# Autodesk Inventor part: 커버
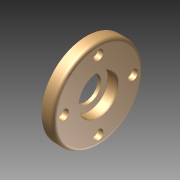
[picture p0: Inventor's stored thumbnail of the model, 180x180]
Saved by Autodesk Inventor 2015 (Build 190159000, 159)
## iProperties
Created: 2024-12
Part Number: 커버
Material: 일반
Document SubType Name: Modeling
Designer: 10401
Density: 1 g/cm^3
Appearance: 기본값
Author: 10401
Author: jhkim
Creation Date: 2024-11-28
Sending System: Autodesk Inventor 2025
Preprocessor: ST-DEVELOPER v20
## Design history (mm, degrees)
node "커버1"
node "솔리드1"
node "기준1"
